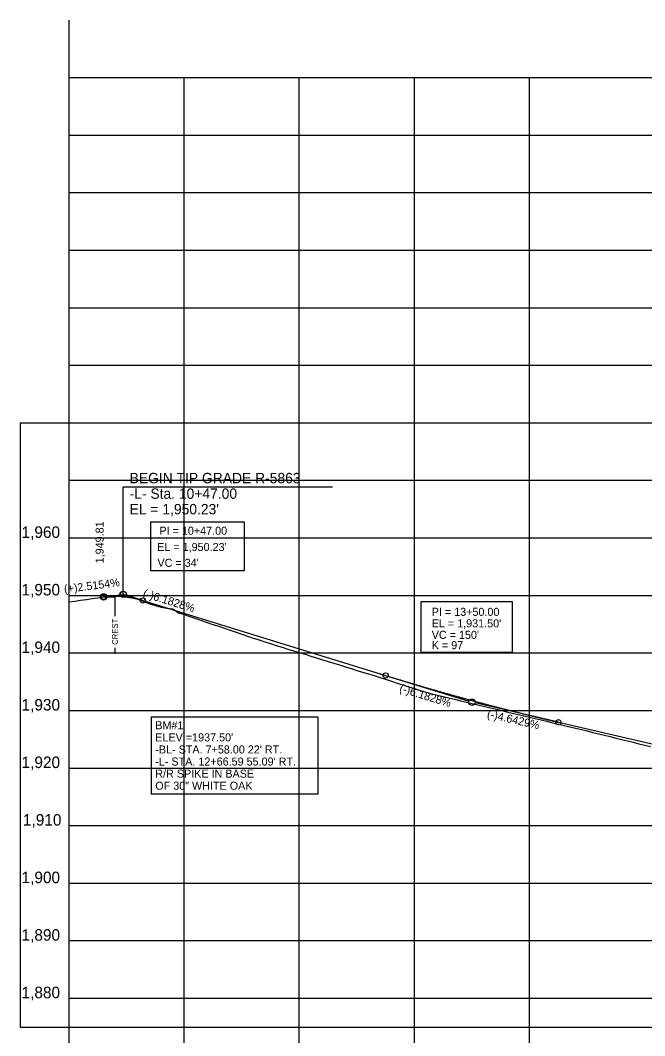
# Model space of a CAD drawing. Extents: x 553912 to 567693, y 512355 to 537539.
# Drawn here: x 557207 to 557749, y 513973 to 514855 of the extents above; entities that cross this region are included whole.
import ezdxf

# ---------------------------------------------------------------- set-up
doc = ezdxf.new("R2010")
doc.units = 0
for name, color, linetype in [('Default', 7, 'Continuous'), ('Exist DTM Spot Elevation Text', 7, 'Continuous'), ('Exist Profile Cell', 7, 'Continuous'), ('Exist Vertical Profile Ground Line', 7, 'Continuous'), ('Exist Vertical Profile Vertical Axis Label', 7, 'Continuous'), ('Prop Vertical Profile Curve Label', 7, 'Continuous'), ('Prop Vertical Profile Grade', 7, 'Continuous'), ('Prop Vertical Profile Grade Label', 7, 'Continuous'), ('Prop VPI Label', 7, 'Continuous'), ('Scratch_Level_5', 7, 'Continuous'), ('Sheet Profile Grid Major CELL', 7, 'Continuous')]:
    doc.layers.add(name, color=color, linetype=linetype)

msp = doc.modelspace()

# ---------------------------------------------------------------- linework, layer by layer
at = {"layer": 'Default'}
for p, q in [((557289.28, 514355.05), (557289.28, 514337.69)), ((557289.28, 514310.25), (557289.28, 514305.05))]:
    msp.add_line(p, q, dxfattribs=at)
at = {"layer": 'Exist DTM Spot Elevation Text'}
msp.add_lwpolyline([(557320.81, 514183.31), (557465.85, 514183.31), (557465.85, 514249.81), (557320.81, 514249.81)], close=True, dxfattribs=at)
at = {"layer": 'Exist Profile Cell'}
msp.add_line((557249.45, 513605.4), (557249.45, 514855.4), dxfattribs=at)
msp.add_line((557249.45, 513605.4), (557249.45, 514855.4), dxfattribs=at)
at = {"layer": 'Exist Vertical Profile Ground Line'}
for points in [[(557249.45, 514350.18), (557254.45, 514350.81), (557259.45, 514351.46), (557264.45, 514352.11), (557269.45, 514352.85), (557274.45, 514353.64), (557279.45, 514354.43), (557284.45, 514354.53), (557289.45, 514354.48), (557294.45, 514357.1), (557299.45, 514356.22), (557304.45, 514354.51), (557309.45, 514352.46), (557314.45, 514350.28), (557319.45, 514348.5), (557324.45, 514346.79), (557329.45, 514345.47), (557334.45, 514344.61), (557339.45, 514344.07), (557344.45, 514340.58), (557349.45, 514338.97), (557354.45, 514337.26), (557359.45, 514335.69), (557364.45, 514333.96), (557369.45, 514332.21), (557374.45, 514330.47), (557379.45, 514328.84), (557384.45, 514327.09), (557389.45, 514325.38), (557394.45, 514323.68), (557399.45, 514321.95), (557404.45, 514320.31), (557409.45, 514318.62), (557414.45, 514317), (557419.45, 514315.37), (557424.45, 514313.77), (557429.45, 514312.17), (557434.45, 514310.63), (557439.45, 514309.06), (557444.45, 514307.55), (557449.45, 514306.01), (557454.45, 514304.49), (557459.45, 514302.9), (557464.45, 514301.35), (557469.45, 514299.79), (557474.45, 514298.27), (557479.45, 514296.71), (557484.45, 514295.23), (557489.45, 514293.68), (557494.45, 514292.13), (557499.45, 514290.57), (557504.45, 514289.05), (557509.45, 514287.52), (557514.45, 514285.98), (557519.45, 514284.38), (557524.45, 514282.78), (557529.45, 514281.17), (557534.45, 514279.56), (557539.45, 514277.95), (557544.45, 514276.34), (557549.45, 514274.73), (557554.45, 514273.13), (557559.45, 514271.61), (557564.45, 514270.24), (557569.45, 514268.94), (557574.45, 514267.76), (557579.45, 514266.57), (557584.45, 514265.38), (557589.45, 514264.2), (557594.45, 514263.01), (557599.45, 514261.83), (557604.45, 514260.64), (557609.45, 514259.44), (557614.45, 514258.23), (557619.45, 514257.03), (557624.45, 514255.82), (557629.45, 514254.62), (557634.45, 514253.41), (557639.45, 514252.2), (557644.45, 514250.99), (557649.45, 514249.77), (557654.45, 514248.6), (557659.45, 514247.43), (557664.45, 514246.26), (557669.45, 514245.09), (557674.45, 514243.93), (557679.45, 514242.75), (557684.45, 514241.58), (557689.45, 514240.4), (557694.45, 514239.16), (557699.45, 514237.92), (557704.45, 514236.67), (557709.45, 514235.43), (557714.45, 514234.18), (557719.45, 514232.94), (557724.45, 514231.7), (557729.45, 514230.45), (557734.45, 514229.23), (557739.45, 514228.01), (557744.45, 514226.79), (557749.45, 514225.56)], [(557249.45, 514350.18), (557254.45, 514350.81), (557259.45, 514351.46), (557264.45, 514352.11), (557269.45, 514352.85), (557274.45, 514353.64), (557279.45, 514354.43), (557284.45, 514354.53), (557289.45, 514354.48), (557294.45, 514357.1), (557299.45, 514356.22), (557304.45, 514354.51), (557309.45, 514352.46), (557314.45, 514350.28), (557319.45, 514348.5), (557324.45, 514346.79), (557329.45, 514345.47), (557334.45, 514344.61), (557339.45, 514344.07), (557344.45, 514340.58), (557349.45, 514338.97), (557354.45, 514337.26), (557359.45, 514335.69), (557364.45, 514333.96), (557369.45, 514332.21), (557374.45, 514330.47), (557379.45, 514328.84), (557384.45, 514327.09), (557389.45, 514325.38), (557394.45, 514323.68), (557399.45, 514321.95), (557404.45, 514320.31), (557409.45, 514318.62), (557414.45, 514317), (557419.45, 514315.37), (557424.45, 514313.77), (557429.45, 514312.17), (557434.45, 514310.63), (557439.45, 514309.06), (557444.45, 514307.55), (557449.45, 514306.01), (557454.45, 514304.49), (557459.45, 514302.9), (557464.45, 514301.35), (557469.45, 514299.79), (557474.45, 514298.27), (557479.45, 514296.71), (557484.45, 514295.23), (557489.45, 514293.68), (557494.45, 514292.13), (557499.45, 514290.57), (557504.45, 514289.05), (557509.45, 514287.52), (557514.45, 514285.98), (557519.45, 514284.38), (557524.45, 514282.78), (557529.45, 514281.17), (557534.45, 514279.56), (557539.45, 514277.95), (557544.45, 514276.34), (557549.45, 514274.73), (557554.45, 514273.13), (557559.45, 514271.61), (557564.45, 514270.24), (557569.45, 514268.94), (557574.45, 514267.76), (557579.45, 514266.57), (557584.45, 514265.38), (557589.45, 514264.2), (557594.45, 514263.01), (557599.45, 514261.83), (557604.45, 514260.64), (557609.45, 514259.44), (557614.45, 514258.23), (557619.45, 514257.03), (557624.45, 514255.82), (557629.45, 514254.62), (557634.45, 514253.41), (557639.45, 514252.2), (557644.45, 514250.99), (557649.45, 514249.77), (557654.45, 514248.6), (557659.45, 514247.43), (557664.45, 514246.26), (557669.45, 514245.09), (557674.45, 514243.93), (557679.45, 514242.75), (557684.45, 514241.58), (557689.45, 514240.4), (557694.45, 514239.16), (557699.45, 514237.92), (557704.45, 514236.67), (557709.45, 514235.43), (557714.45, 514234.18), (557719.45, 514232.94), (557724.45, 514231.7), (557729.45, 514230.45), (557734.45, 514229.23), (557739.45, 514228.01), (557744.45, 514226.79), (557749.45, 514225.56)], [(557749.45, 514225.56), (557754.45, 514224.34)], [(557749.45, 514225.56), (557754.45, 514224.34)]]:
    msp.add_lwpolyline(points, dxfattribs=at)
at = {"layer": 'Prop Vertical Profile Curve Label'}
for centre in [(557279.45, 514354.43), (557313.45, 514351.31), (557524.45, 514286.09), (557674.45, 514245.49)]:
    msp.add_circle(centre, 2.25, dxfattribs=at)
at = {"layer": 'Prop Vertical Profile Grade'}
for p, q in [((557313.45, 514351.31), (557524.45, 514286.09)), ((557674.45, 514245.49), (557779.45, 514221.11))]:
    msp.add_line(p, q, dxfattribs=at)
for points in [[(557279.45, 514354.43), (557280.13, 514354.51), (557280.81, 514354.59), (557281.49, 514354.66), (557282.17, 514354.73), (557282.85, 514354.78), (557283.53, 514354.84), (557284.21, 514354.88), (557284.89, 514354.93), (557285.57, 514354.96), (557286.25, 514354.99), (557286.93, 514355.01), (557287.61, 514355.03), (557288.29, 514355.04), (557288.97, 514355.05), (557289.65, 514355.05), (557290.33, 514355.04), (557291.01, 514355.03), (557291.69, 514355.01), (557292.37, 514354.99), (557293.05, 514354.96), (557293.73, 514354.92), (557294.41, 514354.88), (557295.09, 514354.83), (557295.77, 514354.78), (557296.45, 514354.72), (557297.13, 514354.66), (557297.81, 514354.58), (557298.49, 514354.51), (557299.17, 514354.42), (557299.85, 514354.34), (557300.53, 514354.24), (557301.21, 514354.14), (557301.89, 514354.03), (557302.57, 514353.92), (557303.25, 514353.8), (557303.93, 514353.68), (557304.61, 514353.55), (557305.29, 514353.41), (557305.97, 514353.27), (557306.65, 514353.12), (557307.33, 514352.97), (557308.01, 514352.81), (557308.69, 514352.64), (557309.37, 514352.47), (557310.05, 514352.29), (557310.73, 514352.11), (557311.41, 514351.92), (557312.09, 514351.72), (557312.77, 514351.52), (557313.45, 514351.31)], [(557524.45, 514286.09), (557527.45, 514285.16), (557530.45, 514284.24), (557533.45, 514283.32), (557536.45, 514282.41), (557539.45, 514281.51), (557542.45, 514280.6), (557545.45, 514279.71), (557548.45, 514278.81), (557551.45, 514277.93), (557554.45, 514277.04), (557557.45, 514276.16), (557560.45, 514275.29), (557563.45, 514274.42), (557566.45, 514273.55), (557569.45, 514272.69), (557572.45, 514271.84), (557575.45, 514270.99), (557578.45, 514270.14), (557581.45, 514269.3), (557584.45, 514268.46), (557587.45, 514267.63), (557590.45, 514266.8), (557593.45, 514265.98), (557596.45, 514265.16), (557599.45, 514264.34), (557602.45, 514263.53), (557605.45, 514262.73), (557608.45, 514261.93), (557611.45, 514261.13), (557614.45, 514260.34), (557617.45, 514259.56), (557620.45, 514258.77), (557623.45, 514258), (557626.45, 514257.22), (557629.45, 514256.46), (557632.45, 514255.69), (557635.45, 514254.93), (557638.45, 514254.18), (557641.45, 514253.43), (557644.45, 514252.68), (557647.45, 514251.94), (557650.45, 514251.21), (557653.45, 514250.48), (557656.45, 514249.75), (557659.45, 514249.03), (557662.45, 514248.31), (557665.45, 514247.6), (557668.45, 514246.89), (557671.45, 514246.19), (557674.45, 514245.49)]]:
    msp.add_spline(points, degree=3, dxfattribs=at)
at = {"layer": 'Prop VPI Label'}
for p, q in [((557296.45, 514356.57), (557296.45, 514450.09)), ((557296.45, 514450.09), (557478.2, 514450.09)), ((557279.45, 514354.43), (557293.73, 514356.23)), ((557313.45, 514351.31), (557299.08, 514355.76)), ((557524.45, 514286.09), (557596.83, 514263.71)), ((557674.45, 514245.49), (557602.13, 514262.28))]:
    msp.add_line(p, q, dxfattribs=at)
for points in [[(557320.4, 514419.68), (557401.68, 514419.68), (557401.68, 514377.06), (557320.4, 514377.06)], [(557555.19, 514350.35), (557634.41, 514350.35), (557634.41, 514306.07), (557555.19, 514306.07)]]:
    msp.add_lwpolyline(points, close=True, dxfattribs=at)
for centre in [(557279.45, 514354.43), (557296.45, 514356.57), (557296.45, 514356.57), (557599.45, 514262.9)]:
    msp.add_circle(centre, 2.75, dxfattribs=at)
at = {"layer": 'Scratch_Level_5'}
msp.add_lwpolyline([(557207.08, 514505.4), (557207.08, 513980.4), (558649.45, 513980.4), (558649.45, 514344.35), (558499.4, 514344.35), (558499.4, 514505.4)], close=True, dxfattribs=at)
at = {"layer": 'Sheet Profile Grid Major CELL'}
for p, q in [((563849.45, 514805.4), (557249.45, 514805.4)), ((557249.45, 513605.4), (557249.45, 514805.4)), ((557349.45, 513605.4), (557349.45, 514805.4)), ((557449.45, 513605.4), (557449.45, 514805.4)), ((557549.45, 513605.4), (557549.45, 514805.4)), ((557649.45, 513605.4), (557649.45, 514805.4)), ((563849.45, 514755.4), (557249.45, 514755.4)), ((563849.45, 514705.4), (557249.45, 514705.4)), ((563849.45, 514655.4), (557249.45, 514655.4)), ((563849.45, 514605.4), (557249.45, 514605.4)), ((563849.45, 514555.4), (557249.45, 514555.4)), ((563849.45, 514505.4), (557249.45, 514505.4)), ((563849.45, 514455.4), (557249.45, 514455.4)), ((563849.45, 514405.4), (557249.45, 514405.4)), ((563849.45, 514355.4), (557249.45, 514355.4)), ((563849.45, 514305.4), (557249.45, 514305.4)), ((563849.45, 514255.4), (557249.45, 514255.4)), ((563849.45, 514205.4), (557249.45, 514205.4)), ((563849.45, 514155.4), (557249.45, 514155.4)), ((563849.45, 514105.4), (557249.45, 514105.4)), ((563849.45, 514055.4), (557249.45, 514055.4)), ((563849.45, 514005.4), (557249.45, 514005.4))]:
    msp.add_line(p, q, dxfattribs=at)

# ---------------------------------------------------------------- texts
at = {"layer": 'Default'}
msp.add_text('CREST', height=5, rotation=90, dxfattribs=at).set_placement((557291.78, 514312.75))
at = {"layer": 'Exist DTM Spot Elevation Text'}
for s, p in [('BM#1 ', (557324.31, 514239.31)), ("ELEV.=1937.50'", (557324.31, 514228.81)), ("-BL- STA. 7+58.00 22' RT.", (557324.31, 514218.31)), ("-L- STA. 12+66.59 55.09' RT.", (557324.31, 514207.81)), ('R/R SPIKE IN BASE', (557324.31, 514197.31)), ('OF 30" WHITE OAK', (557324.31, 514186.81))]:
    msp.add_text(s, height=7, dxfattribs=at).set_placement(p)
at = {"layer": 'Exist Vertical Profile Vertical Axis Label'}
for s, p in [('1,960', (557208.15, 514405.65)), ('1,960', (557208.15, 514405.65)), ('1,950', (557208.15, 514355.65)), ('1,950', (557208.15, 514355.65)), ('1,940', (557208.15, 514305.65)), ('1,940', (557208.15, 514305.65)), ('1,930', (557208.15, 514255.65)), ('1,930', (557208.15, 514255.65)), ('1,920', (557208.15, 514205.65)), ('1,920', (557208.15, 514205.65)), ('1,910', (557209.35, 514155.65)), ('1,910', (557209.35, 514155.65)), ('1,900', (557208.15, 514105.65)), ('1,900', (557208.15, 514105.65)), ('1,890', (557208.15, 514055.65)), ('1,890', (557208.15, 514055.65)), ('1,880', (557208.15, 514005.65)), ('1,880', (557208.15, 514005.65))]:
    msp.add_text(s, height=10, dxfattribs=at).set_placement(p)
at = {"layer": 'Prop Vertical Profile Curve Label'}
for s, p in [("VC = 34'", (557326.2, 514380.52)), ("VC = 150'", (557564.45, 514317.9)), ('K = 97', (557564.45, 514308.95))]:
    msp.add_text(s, height=7, dxfattribs=at).set_placement(p)
at = {"layer": 'Prop Vertical Profile Grade Label'}
for s, rotation, p in [('(+)2.5154%', 7.16852, (557245.51, 514357.67)), ('(-)6.1828%', 342.82163, (557313.07, 514354.57)), ('(-)6.1828%', 342.82163, (557535.8, 514272.11)), ('(-)4.6429%', 346.93068, (557612.05, 514249.71))]:
    msp.add_text(s, height=7, rotation=rotation, dxfattribs=at).set_placement(p)
at = {"layer": 'Prop VPI Label'}
for s, height, p in [('BEGIN TIP GRADE R-5863', 9, (557302.04, 514453.13)), ('-L- Sta. 10+47.00', 9, (557302.04, 514439.63)), ("EL = 1,950.23' ", 9, (557302.04, 514426.13)), ('PI = 10+47.00', 7, (557327.9, 514408.37)), ("EL = 1,950.23'", 7, (557325.96, 514394.26)), ('PI = 13+50.00', 7, (557564.45, 514337.9)), ("EL = 1,931.50'", 7, (557564.45, 514327.9))]:
    msp.add_text(s, height=height, dxfattribs=at).set_placement(p)
msp.add_text('1,949.81', height=7, rotation=90, dxfattribs=at).set_placement((557279.45, 514383.54))

doc.saveas('drawing.dxf')
